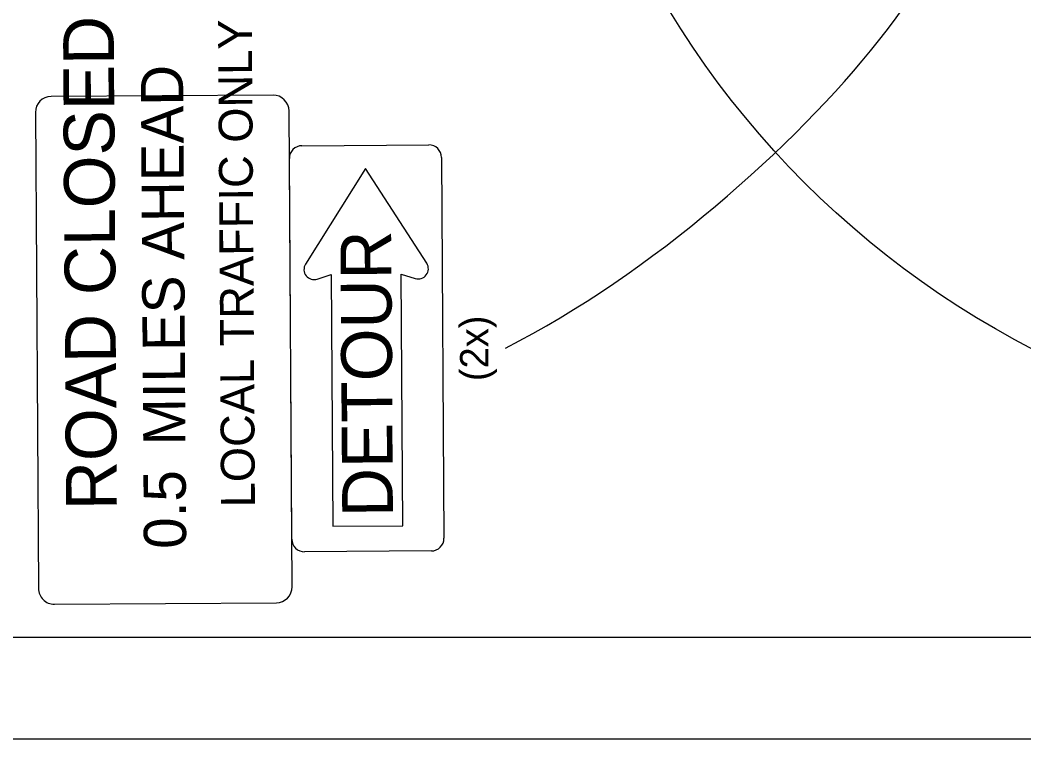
# Model space of a CAD drawing. Extents: x -202 to 1556, y 0 to 676.
# Drawn here: x 51.8 to 150.7, y 0 to 70.8 of the extents above; entities that cross this region are included whole.
import ezdxf

# ---------------------------------------------------------------- set-up
doc = ezdxf.new("R2010")
doc.units = 0
for name, color, linetype in [('Default', 7, 'Continuous'), ('GM_X_Minor_Lake', 7, 'Continuous'), ('GM_X_Minor_Lake_Text', 7, 'Continuous'), ('SH_Border', 7, 'Continuous'), ('SH_Cut_Line', 7, 'Continuous'), ('SH_Data', 7, 'Continuous')]:
    doc.layers.add(name, color=color, linetype=linetype)

msp = doc.modelspace()

# ---------------------------------------------------------------- linework, layer by layer
at = {"layer": 'GM_X_Minor_Lake'}
for p, q in [((85.796, 56.177), (79.883, 46.766)), ((91.83, 46.843), (85.796, 56.177)), ((81.042, 45.284), (82.426, 45.739)), ((82.426, 45.739), (82.586, 20.947)), ((89.461, 20.992), (89.301, 45.783)), ((89.301, 45.783), (90.691, 45.346)), ((82.586, 20.947), (89.461, 20.992))]:
    msp.add_line(p, q, dxfattribs=at)
for points in [[(79.532, 58.429), (92.032, 58.509)], [(78.532, 19.671), (78.29, 57.17)], [(93.29, 57.267), (93.531, 19.768)], [(92.289, 18.51), (79.79, 18.429)]]:
    msp.add_lwpolyline(points, dxfattribs=at)
for centre, radius, start, end in [((79.54, 57.179), 1.25, 90.36941, 180.36941), ((92.04, 57.259), 1.25, 0.36941, 90.36941), ((80.73, 46.234), 1, 147.85856, 288.1883), ((90.991, 46.3), 1, 252.55052, 32.88026), ((79.782, 19.679), 1.25, 180.36941, 270.36941), ((92.281, 19.76), 1.25, 270.36941, 0.36941)]:
    msp.add_arc(centre, radius, start, end, dxfattribs=at)
at = {"layer": 'GM_X_Minor_Lake_Text'}
for points in [[(76.687, 63.41), (54.813, 63.269)], [(53.26, 61.697), (53.562, 14.823)], [(78.562, 14.984), (78.26, 61.858)], [(55.135, 13.27), (77.009, 13.411)]]:
    msp.add_lwpolyline(points, dxfattribs=at)
for centre, start, end in [((76.697, 61.848), 0.36941, 90.36941), ((54.823, 61.707), 90.36941, 180.36941), ((76.999, 14.974), 270.36941, 0.36941), ((55.125, 14.833), 180.36941, 270.36941)]:
    msp.add_arc(centre, 1.563, start, end, dxfattribs=at)
at = {"layer": 'SH_Border'}
msp.add_lwpolyline([(30, 430), (670, 430), (670, 10), (30, 10)], close=True, dxfattribs=at)
at = {"layer": 'SH_Cut_Line'}
msp.add_lwpolyline([(0, 0), (680, 0), (680, 440), (0, 440)], close=True, dxfattribs=at)
at = {"layer": 'SH_Data'}
msp.add_circle((192.681, 118.45), 90, dxfattribs=at)
msp.add_open_spline([(99.584, 38.494), (114.011, 45.821), (142.225, 70.89), (149.271, 95.631), (176.178, 102.836), (190.467, 101.824)], degree=3, dxfattribs=at)

# ---------------------------------------------------------------- texts
at = {"layer": 'Default'}
msp.add_text('(2x)', height=2.8, rotation=90.36941, dxfattribs=at).set_placement((97.926, 35.249))
at = {"layer": 'GM_X_Minor_Lake'}
msp.add_text('DETOUR', height=5, rotation=90.36941, dxfattribs=at).set_placement((88.503, 21.867))
at = {"layer": 'GM_X_Minor_Lake_Text'}
for s, height, p in [('ROAD CLOSED', 5, (61.293, 22.554)), ('LOCAL TRAFFIC ONLY', 3.33333, (74.902, 22.818)), ('MILES AHEAD', 4.16667, (68.057, 28.93)), ('0.5', 4.1667, (68.123, 18.734))]:
    msp.add_text(s, height=height, rotation=90.36941, dxfattribs=at).set_placement(p)

doc.saveas('drawing.dxf')
